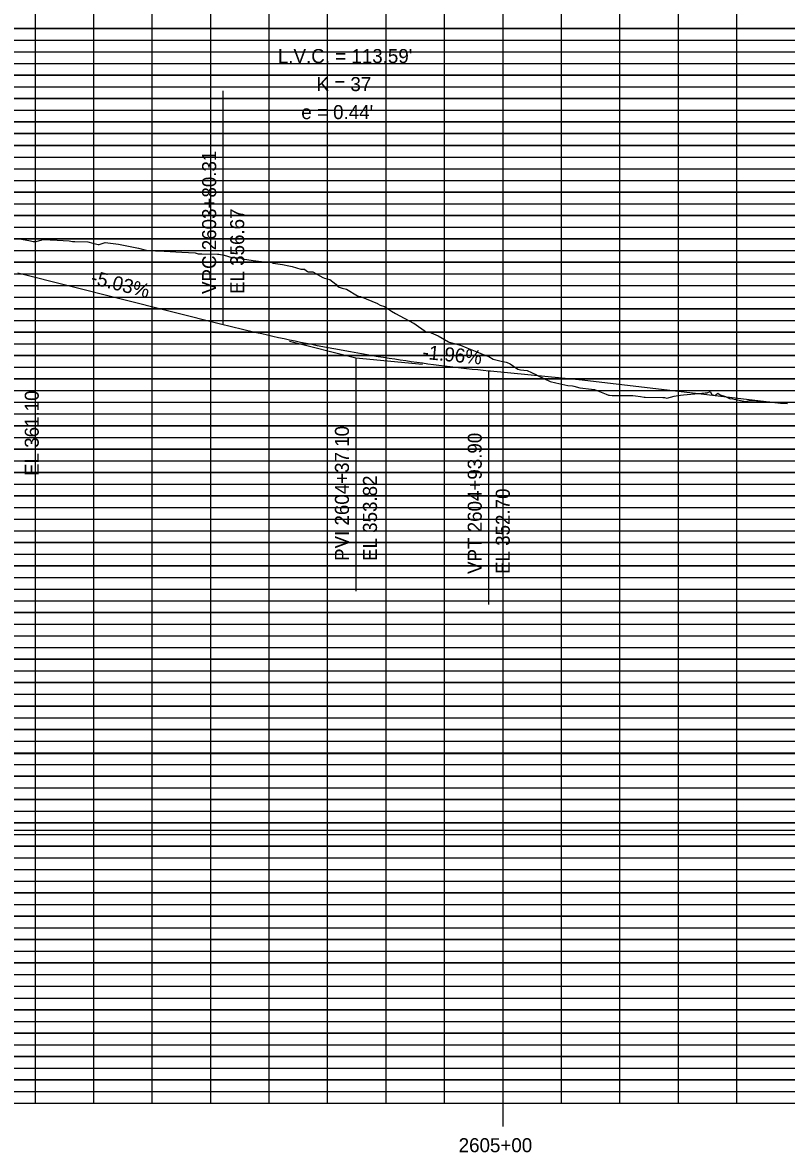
# Model space of a CAD drawing. Extents: x 1195880 to 1289360, y 2059330 to 2086925.
# Drawn here: x 1197294.7 to 1197621.3, y 2063753.6 to 2064237.3 of the extents above; entities that cross this region are included whole.
import ezdxf

# ---------------------------------------------------------------- set-up
doc = ezdxf.new("R2010")
doc.units = 0
for name, color, linetype in [('Clip', 7, 'Continuous'), ('Existing Ground PGL', 7, 'Continuous'), ('Grid', 7, 'Continuous'), ('Grid Lables', 7, 'Continuous'), ('Profile', 7, 'Continuous'), ('Profile Annotation', 7, 'Continuous')]:
    doc.layers.add(name, color=color, linetype=linetype)

msp = doc.modelspace()

# ---------------------------------------------------------------- linework, layer by layer
at = {"layer": 'Clip'}
msp.add_lwpolyline([(1197000.14, 2063924.39), (1197856.43, 2063924.39), (1197856.43, 2064284.72), (1197000.14, 2064284.72)], close=True, dxfattribs=at)
at = {"layer": 'Existing Ground PGL'}
msp.add_lwpolyline([(1197294.22, 2064144.6), (1197298.02, 2064143.78), (1197299.15, 2064143.55), (1197300.47, 2064143.56), (1197301.84, 2064143.96), (1197302.6, 2064144.19), (1197303.39, 2064144.37), (1197309.46, 2064144.08), (1197314.64, 2064143.79), (1197315.97, 2064143.62), (1197317.07, 2064143.58), (1197322.5, 2064143.36), (1197324.69, 2064142.83), (1197327.03, 2064142.25), (1197327.46, 2064142.25), (1197330.01, 2064143.06), (1197332.31, 2064142.8), (1197335.72, 2064142.38), (1197339.93, 2064141.58), (1197344.19, 2064140.74), (1197347.55, 2064139.86), (1197348.17, 2064139.69), (1197351.44, 2064139.56), (1197355.17, 2064139.41), (1197362.79, 2064139.05), (1197368.48, 2064138.75), (1197369.74, 2064138.26), (1197370.41, 2064138.25), (1197371.32, 2064138.22), (1197378.03, 2064138.13), (1197378.54, 2064138.12), (1197380.87, 2064137.75), (1197384.19, 2064136.64), (1197385.65, 2064136.62), (1197388.26, 2064136.56), (1197388.62, 2064136.19), (1197390.6, 2064135.8), (1197393.27, 2064135.46), (1197399.07, 2064134.69), (1197400.88, 2064134.85), (1197400.93, 2064134.85), (1197401.84, 2064134.26), (1197405.8, 2064133.65), (1197408.5, 2064133.13), (1197409.89, 2064132.86), (1197413.66, 2064131.75), (1197415.25, 2064131.71), (1197416.12, 2064131.01), (1197416.31, 2064130.86), (1197416.81, 2064130.58), (1197417.27, 2064130.61), (1197418.83, 2064130.57), (1197423.04, 2064128.14), (1197423.74, 2064127.93), (1197426.04, 2064127.26), (1197428.65, 2064125.33), (1197429.69, 2064124.08), (1197431.36, 2064123.6), (1197433.13, 2064123.1), (1197437.91, 2064120.29), (1197438.98, 2064120.08), (1197439.23, 2064120.03), (1197446.44, 2064117.01), (1197446.6, 2064116.92), (1197447.57, 2064116.34), (1197449.49, 2064115.69), (1197452.44, 2064113.73), (1197454.22, 2064112.75), (1197461.84, 2064108.62), (1197462.01, 2064108.53), (1197467.46, 2064104.76), (1197469.17, 2064104.64), (1197469.46, 2064104.52), (1197472.42, 2064103.21), (1197476.76, 2064100.57), (1197477.07, 2064100.49), (1197481.97, 2064099.24), (1197484.69, 2064098.1), (1197488.94, 2064096.34), (1197492.31, 2064094.95), (1197494.03, 2064094.26), (1197495.89, 2064093.12), (1197499.93, 2064092.24), (1197500.01, 2064092.22), (1197501.45, 2064091.86), (1197501.9, 2064091.72), (1197503.15, 2064091.25), (1197506.53, 2064088.85), (1197507.55, 2064088.67), (1197507.66, 2064088.65), (1197510.45, 2064088.3), (1197514.17, 2064086.57), (1197515.17, 2064086.09), (1197520.29, 2064083.62), (1197522.79, 2064083.08), (1197527.8, 2064081.98), (1197529.91, 2064081.77), (1197530.41, 2064081.62), (1197532.93, 2064080.86), (1197538.03, 2064080.33), (1197539.25, 2064080.2), (1197544.31, 2064078.22), (1197545.26, 2064077.78), (1197545.65, 2064077.73), (1197546.78, 2064077.58), (1197553.27, 2064077.64), (1197555.69, 2064077.65), (1197556.84, 2064077.46), (1197558.97, 2064077.23), (1197560.56, 2064076.98), (1197560.88, 2064076.98), (1197568.5, 2064076.83), (1197569.21, 2064076.81), (1197570.26, 2064076.52), (1197573.3, 2064077.31), (1197573.39, 2064077.31), (1197576.12, 2064077.74), (1197577.39, 2064077.94), (1197583.74, 2064078.53), (1197586.54, 2064078.78), (1197587.09, 2064078.78), (1197587.49, 2064078.71), (1197588.72, 2064079.28), (1197589.41, 2064078.02), (1197590.29, 2064077.75), (1197590.87, 2064077.61), (1197591.36, 2064078.03), (1197592.01, 2064078.58), (1197593.07, 2064077.93), (1197595.32, 2064077.22), (1197597.29, 2064076.24), (1197597.88, 2064076.28), (1197598.98, 2064076.07), (1197603.8, 2064075.1), (1197604.05, 2064075.11), (1197605.6, 2064075.52), (1197606.6, 2064075.45), (1197614.22, 2064074.86), (1197615.8, 2064074.74), (1197618.83, 2064074.4), (1197619.56, 2064074.35), (1197621.84, 2064074.15)], dxfattribs=at)
at = {"layer": 'Grid'}
for p, q in [((1197300.14, 2063774.72), (1197300.14, 2064474.72)), ((1197325.14, 2063774.72), (1197325.14, 2064474.72)), ((1197350.14, 2063774.72), (1197350.14, 2064474.72)), ((1197375.14, 2063774.72), (1197375.14, 2064474.72)), ((1197400.14, 2063774.72), (1197400.14, 2064474.72)), ((1197425.14, 2063774.72), (1197425.14, 2064474.72)), ((1197450.14, 2063774.72), (1197450.14, 2064474.72)), ((1197475.14, 2063774.72), (1197475.14, 2064474.72)), ((1197500.14, 2063774.72), (1197500.14, 2064474.72)), ((1197525.14, 2063774.72), (1197525.14, 2064474.72)), ((1197550.14, 2063774.72), (1197550.14, 2064474.72)), ((1197575.14, 2063774.72), (1197575.14, 2064474.72)), ((1197600.14, 2063774.72), (1197600.14, 2064474.72)), ((1197000.14, 2064234.72), (1198000.14, 2064234.72)), ((1198000.14, 2064234.72), (1197000.14, 2064234.72)), ((1197000.14, 2064229.72), (1198000.14, 2064229.72)), ((1197000.14, 2064224.72), (1198000.14, 2064224.72)), ((1197000.14, 2064219.72), (1198000.14, 2064219.72)), ((1197000.14, 2064214.72), (1198000.14, 2064214.72)), ((1198000.14, 2064214.72), (1197000.14, 2064214.72)), ((1197000.14, 2064209.72), (1198000.14, 2064209.72)), ((1197000.14, 2064204.72), (1198000.14, 2064204.72)), ((1198000.14, 2064204.72), (1197000.14, 2064204.72)), ((1197000.14, 2064199.72), (1198000.14, 2064199.72)), ((1197000.14, 2064194.72), (1198000.14, 2064194.72)), ((1198000.14, 2064194.72), (1197000.14, 2064194.72)), ((1198000.14, 2064189.77), (1197000.14, 2064189.77)), ((1197000.14, 2064189.72), (1198000.14, 2064189.72)), ((1197000.14, 2064184.72), (1198000.14, 2064184.72)), ((1198000.14, 2064184.72), (1197000.14, 2064184.72)), ((1197000.14, 2064179.72), (1198000.14, 2064179.72)), ((1197000.14, 2064174.72), (1198000.14, 2064174.72)), ((1197000.14, 2064169.72), (1198000.14, 2064169.72)), ((1197000.14, 2064164.72), (1198000.14, 2064164.72)), ((1198000.14, 2064164.72), (1197000.14, 2064164.72)), ((1197000.14, 2064159.72), (1198000.14, 2064159.72)), ((1197000.14, 2064154.72), (1198000.14, 2064154.72)), ((1198000.14, 2064154.72), (1197000.14, 2064154.72)), ((1197000.14, 2064149.72), (1198000.14, 2064149.72)), ((1197000.14, 2064144.72), (1198000.14, 2064144.72)), ((1198000.14, 2064144.72), (1197000.14, 2064144.72)), ((1197000.14, 2064139.72), (1198000.14, 2064139.72)), ((1197000.14, 2064134.72), (1198000.14, 2064134.72)), ((1198000.14, 2064134.72), (1197000.14, 2064134.72)), ((1197000.14, 2064129.72), (1198000.14, 2064129.72)), ((1197000.14, 2064124.72), (1198000.14, 2064124.72)), ((1197000.14, 2064119.72), (1198000.14, 2064119.72)), ((1197000.14, 2064114.72), (1198000.14, 2064114.72)), ((1198000.14, 2064114.72), (1197000.14, 2064114.72)), ((1197000.14, 2064109.72), (1198000.14, 2064109.72)), ((1197000.14, 2064104.72), (1198000.14, 2064104.72)), ((1198000.14, 2064104.72), (1197000.14, 2064104.72)), ((1197000.14, 2064099.72), (1198000.14, 2064099.72)), ((1197000.14, 2064094.72), (1198000.14, 2064094.72)), ((1198000.14, 2064094.72), (1197000.14, 2064094.72)), ((1197000.14, 2064089.72), (1198000.14, 2064089.72)), ((1197000.14, 2064084.72), (1198000.14, 2064084.72)), ((1198000.14, 2064084.72), (1197000.14, 2064084.72)), ((1197000.14, 2064079.72), (1198000.14, 2064079.72)), ((1197000.14, 2064074.72), (1198000.14, 2064074.72)), ((1197000.14, 2064069.72), (1198000.14, 2064069.72)), ((1197000.14, 2064064.72), (1198000.14, 2064064.72)), ((1198000.14, 2064064.72), (1197000.14, 2064064.72)), ((1197000.14, 2064059.72), (1198000.14, 2064059.72)), ((1197000.14, 2064054.72), (1198000.14, 2064054.72)), ((1198000.14, 2064054.72), (1197000.14, 2064054.72)), ((1197000.14, 2064049.72), (1198000.14, 2064049.72)), ((1197000.14, 2064044.72), (1198000.14, 2064044.72)), ((1198000.14, 2064044.72), (1197000.14, 2064044.72)), ((1197000.14, 2064039.72), (1198000.14, 2064039.72)), ((1197000.14, 2064034.72), (1198000.14, 2064034.72)), ((1198000.14, 2064034.72), (1197000.14, 2064034.72)), ((1197000.14, 2064029.72), (1198000.14, 2064029.72)), ((1197000.14, 2064024.72), (1198000.14, 2064024.72)), ((1197000.14, 2064019.72), (1198000.14, 2064019.72)), ((1197000.14, 2064014.72), (1198000.14, 2064014.72)), ((1198000.14, 2064014.72), (1197000.14, 2064014.72)), ((1197000.14, 2064009.72), (1198000.14, 2064009.72)), ((1197000.14, 2064004.72), (1198000.14, 2064004.72)), ((1198000.14, 2064004.72), (1197000.14, 2064004.72)), ((1197000.14, 2063999.72), (1198000.14, 2063999.72)), ((1197000.14, 2063994.72), (1198000.14, 2063994.72)), ((1197000.14, 2063989.72), (1198000.14, 2063989.72)), ((1197000.14, 2063984.72), (1198000.14, 2063984.72)), ((1198000.14, 2063984.72), (1197000.14, 2063984.72)), ((1197000.14, 2063979.72), (1198000.14, 2063979.72)), ((1197000.14, 2063974.72), (1198000.14, 2063974.72)), ((1197000.14, 2063969.72), (1198000.14, 2063969.72)), ((1197000.14, 2063964.72), (1198000.14, 2063964.72)), ((1198000.14, 2063964.72), (1197000.14, 2063964.72)), ((1197000.14, 2063959.72), (1198000.14, 2063959.72)), ((1197000.14, 2063954.72), (1198000.14, 2063954.72)), ((1198000.14, 2063954.72), (1197000.14, 2063954.72)), ((1197000.14, 2063949.72), (1198000.14, 2063949.72)), ((1197000.14, 2063944.72), (1198000.14, 2063944.72)), ((1198000.14, 2063944.72), (1197000.14, 2063944.72)), ((1197000.14, 2063939.72), (1198000.14, 2063939.72)), ((1197000.14, 2063934.72), (1198000.14, 2063934.72)), ((1198000.14, 2063934.72), (1197000.14, 2063934.72)), ((1197000.14, 2063929.72), (1198000.14, 2063929.72)), ((1197000.14, 2063924.72), (1198000.14, 2063924.72)), ((1197000.14, 2063919.72), (1198000.14, 2063919.72)), ((1197000.14, 2063914.72), (1198000.14, 2063914.72)), ((1198000.14, 2063914.72), (1197000.14, 2063914.72)), ((1197000.14, 2063909.72), (1198000.14, 2063909.72)), ((1197000.14, 2063904.72), (1198000.14, 2063904.72)), ((1198000.14, 2063904.72), (1197000.14, 2063904.72)), ((1197000.14, 2063899.72), (1198000.14, 2063899.72)), ((1197000.14, 2063894.72), (1198000.14, 2063894.72)), ((1198000.14, 2063894.72), (1197000.14, 2063894.72)), ((1198000.14, 2063891.49), (1197000.14, 2063891.49)), ((1197000.14, 2063889.72), (1198000.14, 2063889.72)), ((1197000.14, 2063884.72), (1198000.14, 2063884.72)), ((1198000.14, 2063884.72), (1197000.14, 2063884.72)), ((1197000.14, 2063879.72), (1198000.14, 2063879.72)), ((1197000.14, 2063874.72), (1198000.14, 2063874.72)), ((1197000.14, 2063869.72), (1198000.14, 2063869.72)), ((1197000.14, 2063864.72), (1198000.14, 2063864.72)), ((1198000.14, 2063864.72), (1197000.14, 2063864.72)), ((1197000.14, 2063859.72), (1198000.14, 2063859.72)), ((1197000.14, 2063854.72), (1198000.14, 2063854.72)), ((1198000.14, 2063854.72), (1197000.14, 2063854.72)), ((1197000.14, 2063849.72), (1198000.14, 2063849.72)), ((1197000.14, 2063844.72), (1198000.14, 2063844.72)), ((1198000.14, 2063844.72), (1197000.14, 2063844.72)), ((1197000.14, 2063839.72), (1198000.14, 2063839.72)), ((1197000.14, 2063834.72), (1198000.14, 2063834.72)), ((1198000.14, 2063834.72), (1197000.14, 2063834.72)), ((1197000.14, 2063829.72), (1198000.14, 2063829.72)), ((1197000.14, 2063824.72), (1198000.14, 2063824.72)), ((1197000.14, 2063819.72), (1198000.14, 2063819.72)), ((1197000.14, 2063814.72), (1198000.14, 2063814.72)), ((1198000.14, 2063814.72), (1197000.14, 2063814.72)), ((1197000.14, 2063809.72), (1198000.14, 2063809.72)), ((1197000.14, 2063804.72), (1198000.14, 2063804.72)), ((1198000.14, 2063804.72), (1197000.14, 2063804.72)), ((1197000.14, 2063799.72), (1198000.14, 2063799.72)), ((1197000.14, 2063794.72), (1198000.14, 2063794.72)), ((1198000.14, 2063794.72), (1197000.14, 2063794.72)), ((1197000.14, 2063789.72), (1198000.14, 2063789.72)), ((1197000.14, 2063784.72), (1198000.14, 2063784.72)), ((1198000.14, 2063784.72), (1197000.14, 2063784.72)), ((1197000.14, 2063779.72), (1198000.14, 2063779.72)), ((1197000.14, 2063774.72), (1198000.14, 2063774.72)), ((1197300.14, 2063774.72), (1197300.14, 2063777.72)), ((1197325.14, 2063774.72), (1197325.14, 2063777.72)), ((1197350.14, 2063774.72), (1197350.14, 2063777.72)), ((1197375.14, 2063774.72), (1197375.14, 2063777.72)), ((1197400.14, 2063774.72), (1197400.14, 2063777.72)), ((1197425.14, 2063774.72), (1197425.14, 2063777.72)), ((1197450.14, 2063774.72), (1197450.14, 2063777.72)), ((1197475.14, 2063774.72), (1197475.14, 2063777.72)), ((1197500.14, 2063764.72), (1197500.14, 2063774.72)), ((1197525.14, 2063774.72), (1197525.14, 2063777.72)), ((1197550.14, 2063774.72), (1197550.14, 2063777.72)), ((1197575.14, 2063774.72), (1197575.14, 2063777.72)), ((1197600.14, 2063774.72), (1197600.14, 2063777.72))]:
    msp.add_line(p, q, dxfattribs=at)
at = {"layer": 'Profile'}
for p, q in [((1197292.57, 2064130.2), (1197380.45, 2064108.09)), ((1197494.04, 2064088.24), (1197494.76, 2064088.17)), ((1197494.76, 2064088.17), (1197534.03, 2064084.32)), ((1197534.03, 2064084.32), (1197617.54, 2064074.55))]:
    msp.add_line(p, q, dxfattribs=at)
msp.add_lwpolyline([(1197380.45, 2064108.09), (1197382.81, 2064107.5), (1197385.18, 2064106.92), (1197387.55, 2064106.34), (1197389.91, 2064105.77), (1197392.28, 2064105.21), (1197394.65, 2064104.66), (1197397.01, 2064104.11), (1197399.38, 2064103.57), (1197401.75, 2064103.04), (1197404.11, 2064102.52), (1197406.48, 2064102), (1197408.84, 2064101.49), (1197411.21, 2064100.99), (1197413.58, 2064100.5), (1197415.94, 2064100.01), (1197418.31, 2064099.54), (1197420.68, 2064099.07), (1197423.04, 2064098.6), (1197425.41, 2064098.15), (1197427.78, 2064097.7), (1197430.14, 2064097.26), (1197432.51, 2064096.83), (1197434.88, 2064096.4), (1197439.61, 2064095.57), (1197441.97, 2064095.17), (1197444.34, 2064094.78), (1197446.71, 2064094.39), (1197449.07, 2064094.01), (1197451.44, 2064093.64), (1197453.81, 2064093.27), (1197456.17, 2064092.92), (1197458.54, 2064092.57), (1197460.91, 2064092.23), (1197463.27, 2064091.89), (1197465.64, 2064091.57), (1197468, 2064091.25), (1197470.37, 2064090.94), (1197472.74, 2064090.63), (1197475.1, 2064090.34), (1197477.47, 2064090.05), (1197479.84, 2064089.77), (1197482.2, 2064089.49), (1197484.57, 2064089.23), (1197486.94, 2064088.97), (1197489.3, 2064088.72), (1197491.67, 2064088.47), (1197494.04, 2064088.24)], dxfattribs=at)
at = {"layer": 'Profile Annotation'}
for p, q in [((1197380.45, 2064108.09), (1197380.45, 2064208.09)), ((1197408.84, 2064100.95), (1197437.24, 2064093.81)), ((1197437.24, 2064093.81), (1197465.64, 2064091.02)), ((1197437.24, 2064093.81), (1197437.24, 2063993.81)), ((1197494.04, 2063988.24), (1197494.04, 2064088.24))]:
    msp.add_line(p, q, dxfattribs=at)

# ---------------------------------------------------------------- texts
at = {"layer": 'Grid Lables'}
msp.add_text('2605+00', height=6, dxfattribs=at).set_placement((1197481.17, 2063753.72))
at = {"layer": 'Profile Annotation'}
for s, p in [("L.V.C. = 113.59'", (1197403.85, 2064219.94)), ('K = 37', (1197420.38, 2064207.94)), ("e = 0.44'", (1197413.86, 2064195.94))]:
    msp.add_text(s, height=6, dxfattribs=at).set_placement(p)
for s, rotation, p in [('VPC 2603+80.31', 90, (1197377.45, 2064121.09)), ('EL 356.67', 90, (1197389.45, 2064121.09)), ('-5.03%', 345.881, (1197323.47, 2064125.52)), ('-1.96%', 354.4007, (1197465.51, 2064093.36)), ('EL 361.10', 90, (1197301.57, 2064043.2)), ('PVI 2604+37.10', 90, (1197434.24, 2064006.81)), ('VPT 2604+93.90', 90, (1197491.04, 2064001.24)), ('EL 353.82', 90, (1197446.24, 2064006.81)), ('EL 352.70', 90, (1197503.04, 2064001.24))]:
    msp.add_text(s, height=6, rotation=rotation, dxfattribs=at).set_placement(p)

doc.saveas('drawing.dxf')
